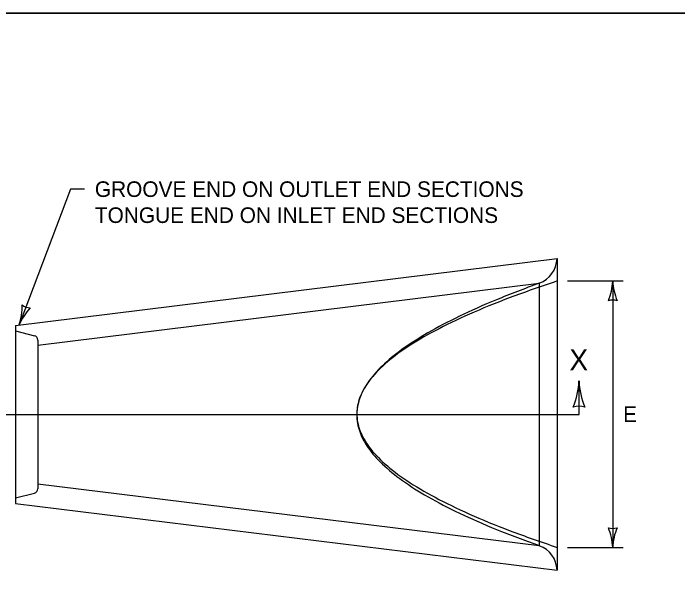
# Model space of a CAD drawing. Extents: x 49991.4 to 50021, y 49987.6 to 50011.4.
# Drawn here: x 50000.675 to 50003.231, y 49996.829 to 49998.999 of the extents above; entities that cross this region are included whole.
import ezdxf

# ---------------------------------------------------------------- set-up
doc = ezdxf.new("R2010")
doc.units = 0
for name, color, linetype in [('Level 1', 7, 'Continuous'), ('Level 2', 7, 'Continuous'), ('Level 3', 7, 'Continuous'), ('Level 4', 7, 'Continuous'), ('Level 6', 7, 'Continuous')]:
    doc.layers.add(name, color=color, linetype=linetype)

msp = doc.modelspace()

# ---------------------------------------------------------------- linework, layer by layer
at = {"layer": 'Level 1'}
for p, q in [((50000.6836, 49997.7995), (50002.7668, 49998.0564)), ((50002.7668, 49998.0564), (50002.7668, 49996.8577)), ((50002.6983, 49997.9616), (50002.6983, 49996.9525)), ((50000.6836, 49997.7995), (50000.6836, 49997.1146)), ((50000.6836, 49997.1146), (50002.7668, 49996.8577))]:
    msp.add_line(p, q, dxfattribs=at)
msp.add_lwpolyline([(49999.3835, 49998.9992), (50016.7501, 49998.9992), (50016.7501, 49987.7988), (49999.3835, 49987.7988)], close=True, dxfattribs=at)
for centre, start, end in [((50002.6624, 49998.0597), 290.0929, 358.1486), ((50002.6624, 49996.8544), 1.8514, 69.9071)]:
    msp.add_arc(centre, 0.1044, start, end, dxfattribs=at)
for points in [[(50002.7668, 49997.9701), (50001.226, 49997.46), (50002.7668, 49996.9456)], [(50002.6983, 49997.9616), (50001.2942, 49997.4525), (50002.6983, 49996.9525)]]:
    msp.add_open_spline(points, degree=2, dxfattribs=at)
at = {"layer": 'Level 2'}
msp.add_line((50016.7501, 49998.9992), (49999.3835, 49998.9992), dxfattribs=at)
at = {"layer": 'Level 3'}
for p, q in [((50000.8947, 49998.3231), (50000.6976, 49997.8012)), ((50000.9485, 49998.3231), (50000.8947, 49998.3231)), ((50002.8068, 49997.9701), (50003.0208, 49997.9701)), ((50002.9808, 49997.9701), (50002.9808, 49996.9456)), ((50002.8068, 49996.9456), (50003.0208, 49996.9456))]:
    msp.add_line(p, q, dxfattribs=at)
for centre, radius, start, end in [((50002.7587, 49997.9793), 0.2223, 337.456, 357.6395), ((50003.2135, 49997.9816), 0.233, 182.8273, 202.0772), ((50002.9808, 49997.8419), 0.0548, 72.1388, 107.8612), ((50000.4758, 49997.8727), 0.233, 342.1298, 1.3797), ((50000.9021, 49997.7141), 0.2223, 136.7585, 156.942), ((50000.7429, 49997.9212), 0.0548, 231.4413, 267.1637), ((50002.5549, 49997.599), 0.2964, 337.456, 357.6395), ((50003.1614, 49997.6021), 0.3107, 182.8273, 202.0772), ((50002.8511, 49997.4158), 0.073, 72.1388, 107.8612), ((50002.9808, 49997.0738), 0.0548, 252.1388, 287.8612), ((50002.7481, 49996.9341), 0.233, 2.8273, 22.0772), ((50003.2029, 49996.9364), 0.2223, 157.456, 177.6395)]:
    msp.add_arc(centre, radius, start, end, dxfattribs=at)
at = {"layer": 'Level 4'}
for p, q in [((50000.7692, 49997.7238), (50002.6983, 49997.9616)), ((50000.6836, 49997.778), (50000.7562, 49997.7596)), ((50000.7692, 49997.743), (50000.7692, 49997.1711)), ((50000.7692, 49997.1904), (50002.6983, 49996.9525)), ((50000.6836, 49997.1361), (50000.7562, 49997.1545))]:
    msp.add_line(p, q, dxfattribs=at)
for centre, start, end in [((50000.7521, 49997.743), 0, 75.8416), ((50000.7521, 49997.1711), 284.1569, 0)]:
    msp.add_arc(centre, 0.0171, start, end, dxfattribs=at)
at = {"layer": 'Level 6'}
for p, q in [((50002.8511, 49997.457), (50002.8511, 49997.5868)), ((50000.5813, 49997.457), (50002.8511, 49997.457))]:
    msp.add_line(p, q, dxfattribs=at)

# ---------------------------------------------------------------- texts
at = {"layer": 'Level 2'}
for s, height, p in [('GROOVE END ON OUTLET END SECTIONS', 0.06, (50000.9885, 49998.2931)), ('TONGUE END ON INLET END SECTIONS', 0.06, (50000.9885, 49998.1931)), ('X', 0.08, (50002.8144, 49997.6268)), ('E', 0.06, (50003.0208, 49997.4278))]:
    msp.add_text(s, height=height, dxfattribs=at).set_placement(p)

doc.saveas('drawing.dxf')
